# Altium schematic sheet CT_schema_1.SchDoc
size 750 x 499 mm
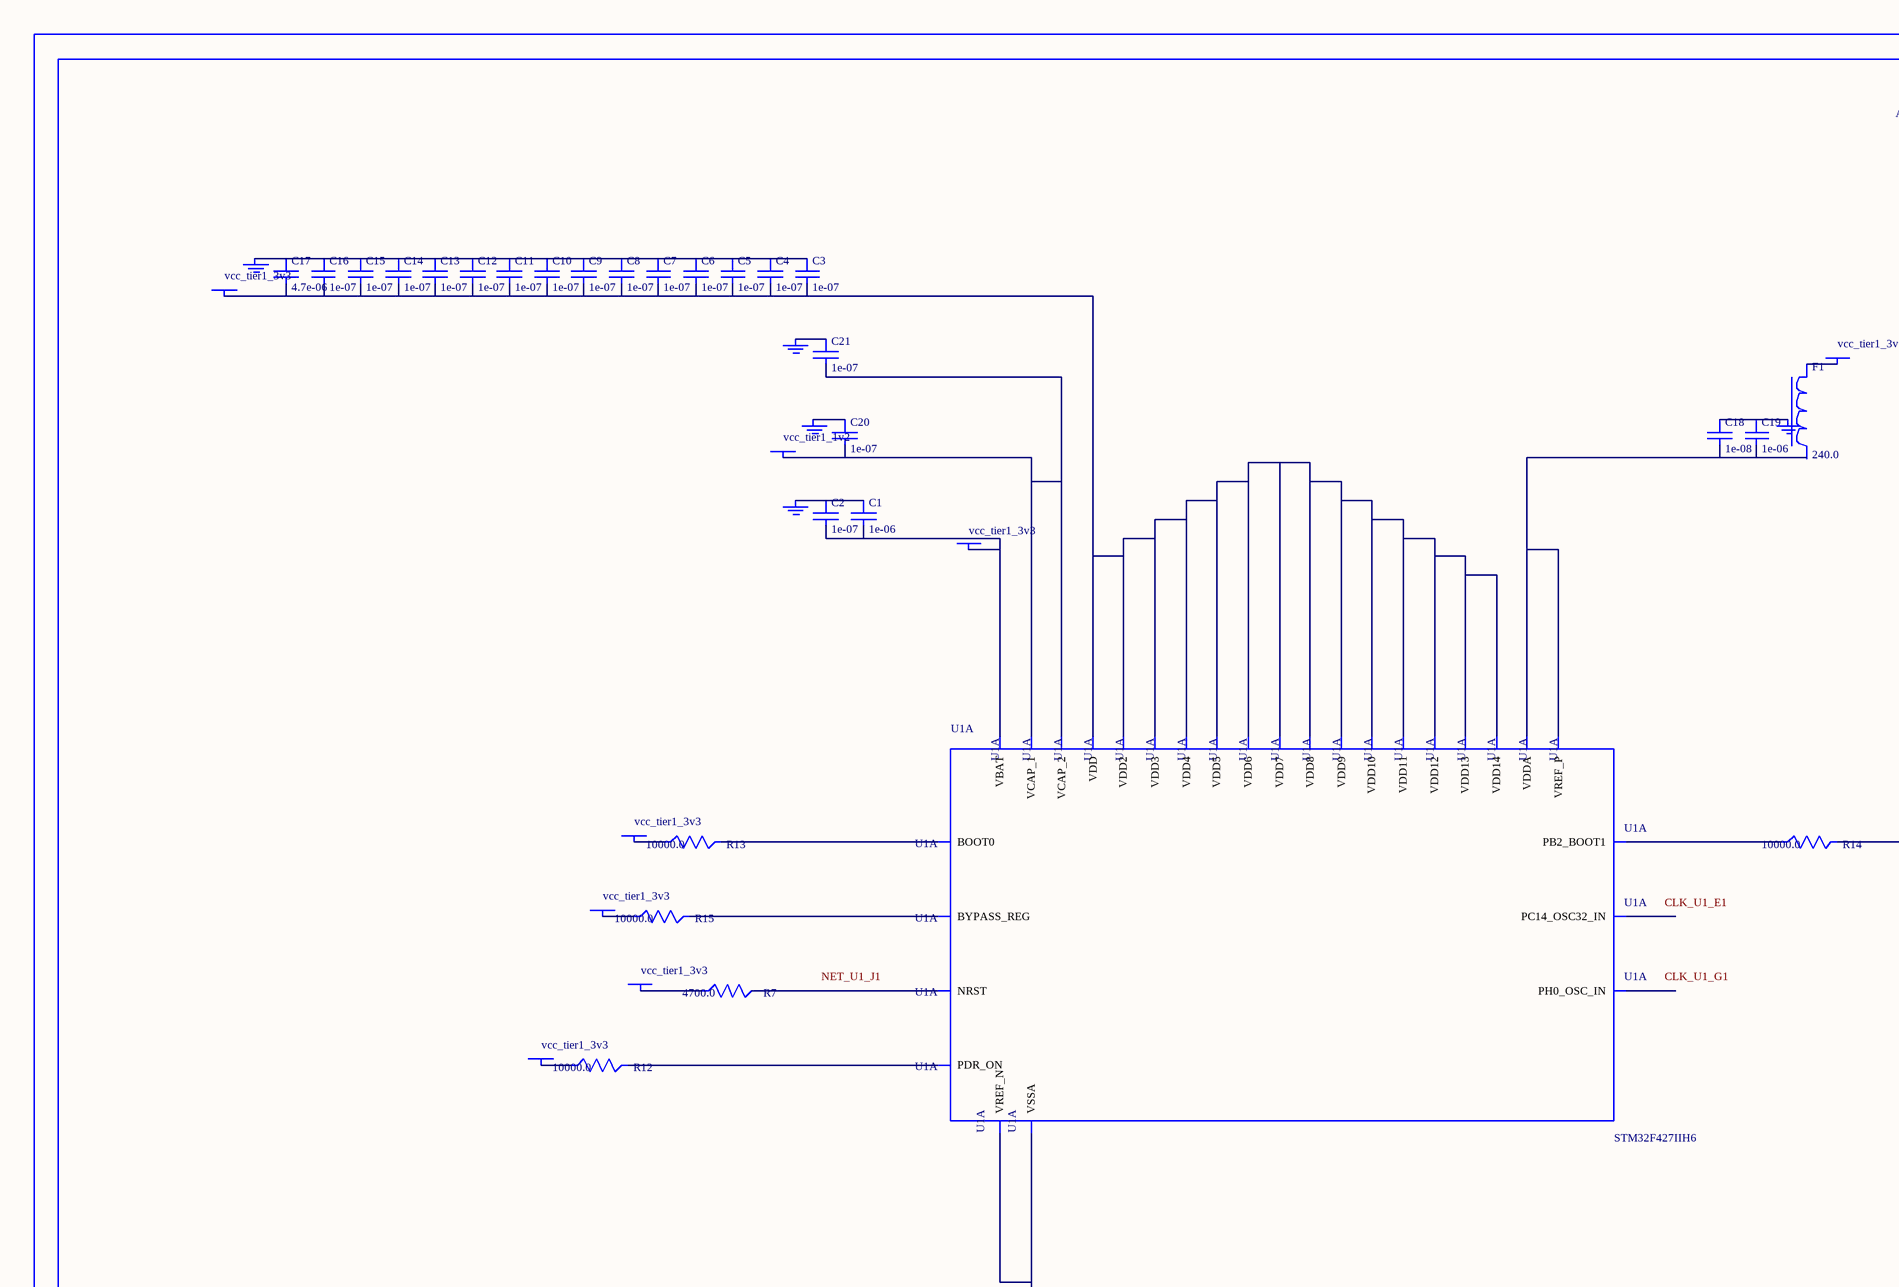
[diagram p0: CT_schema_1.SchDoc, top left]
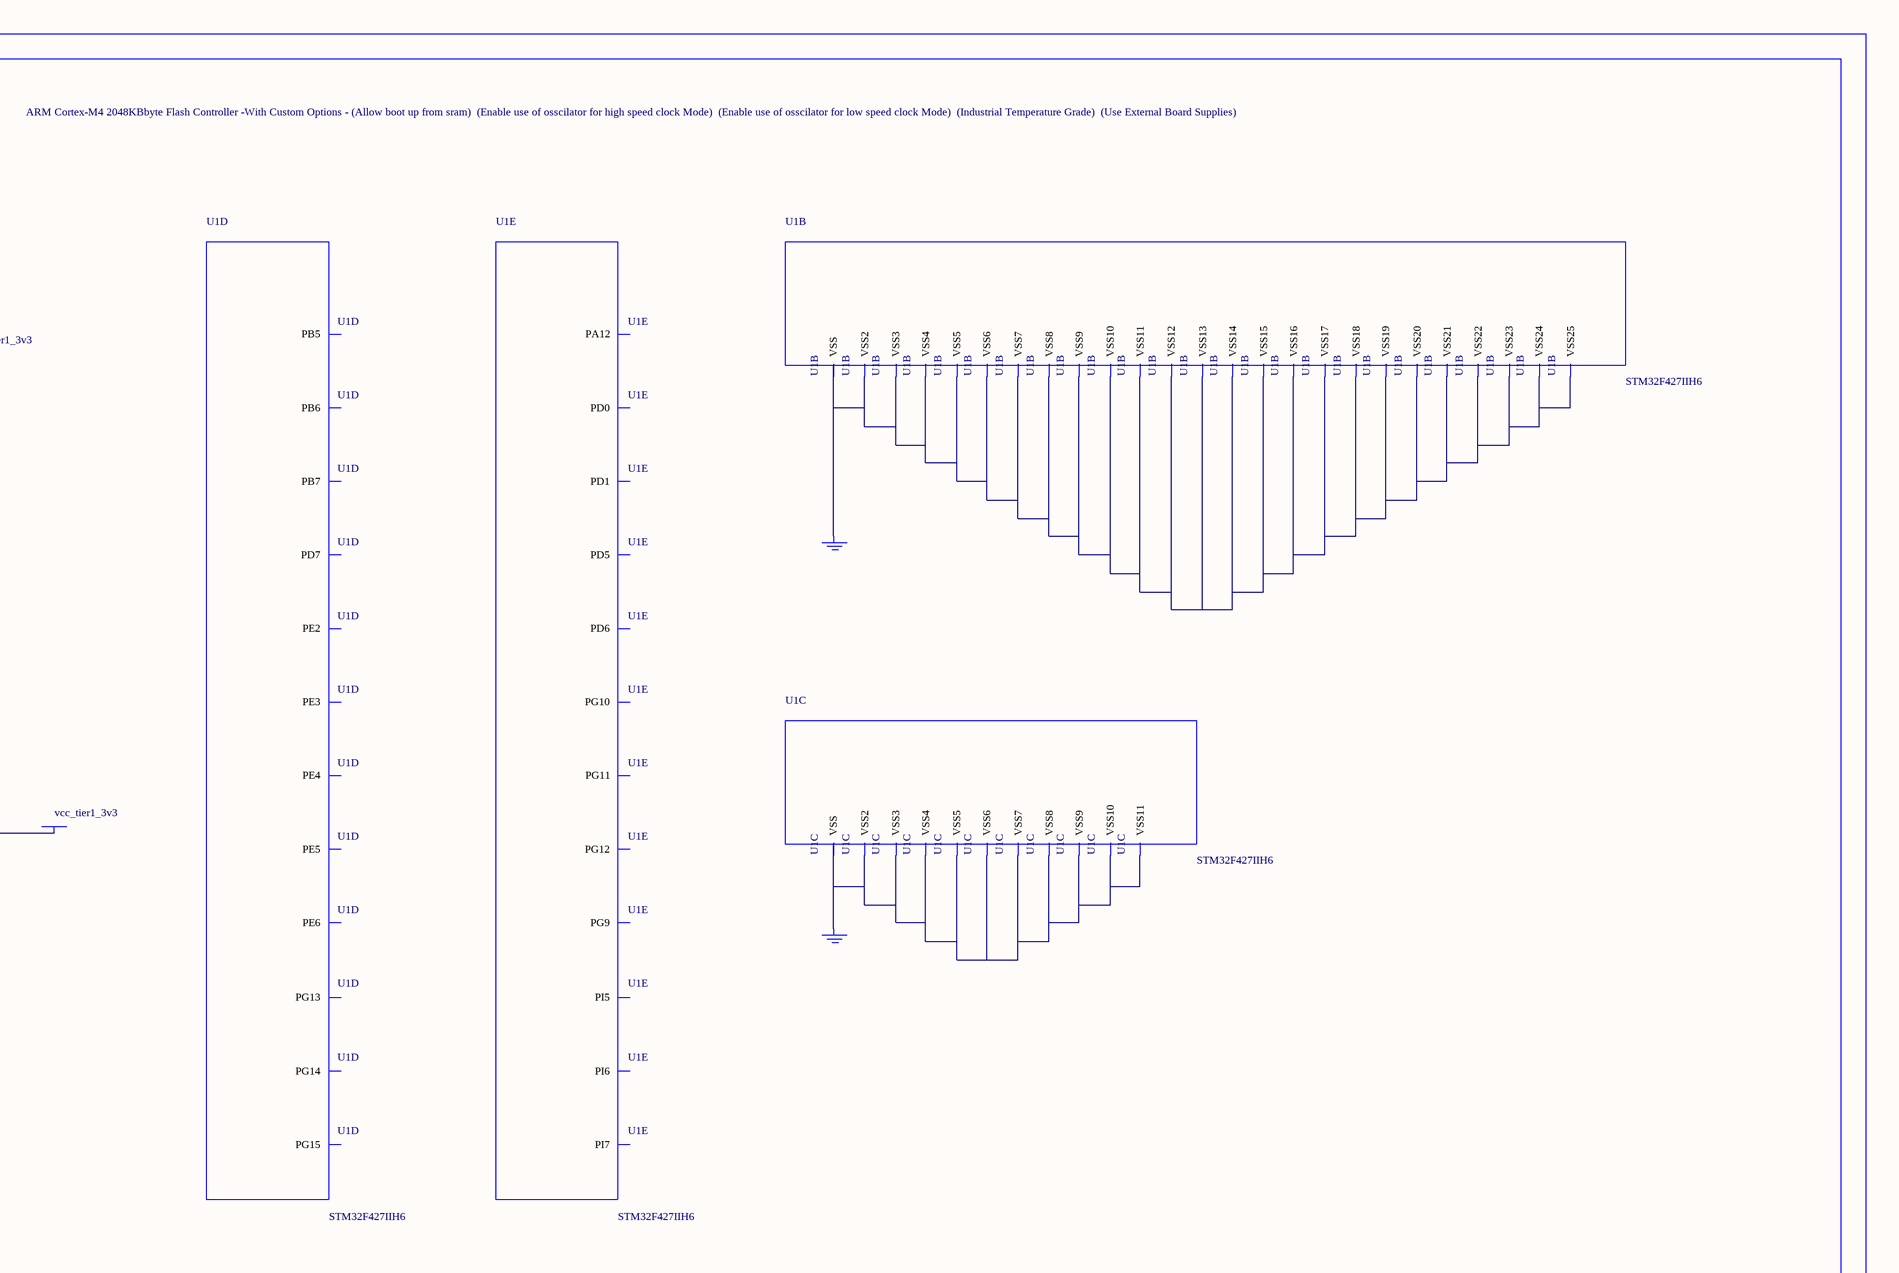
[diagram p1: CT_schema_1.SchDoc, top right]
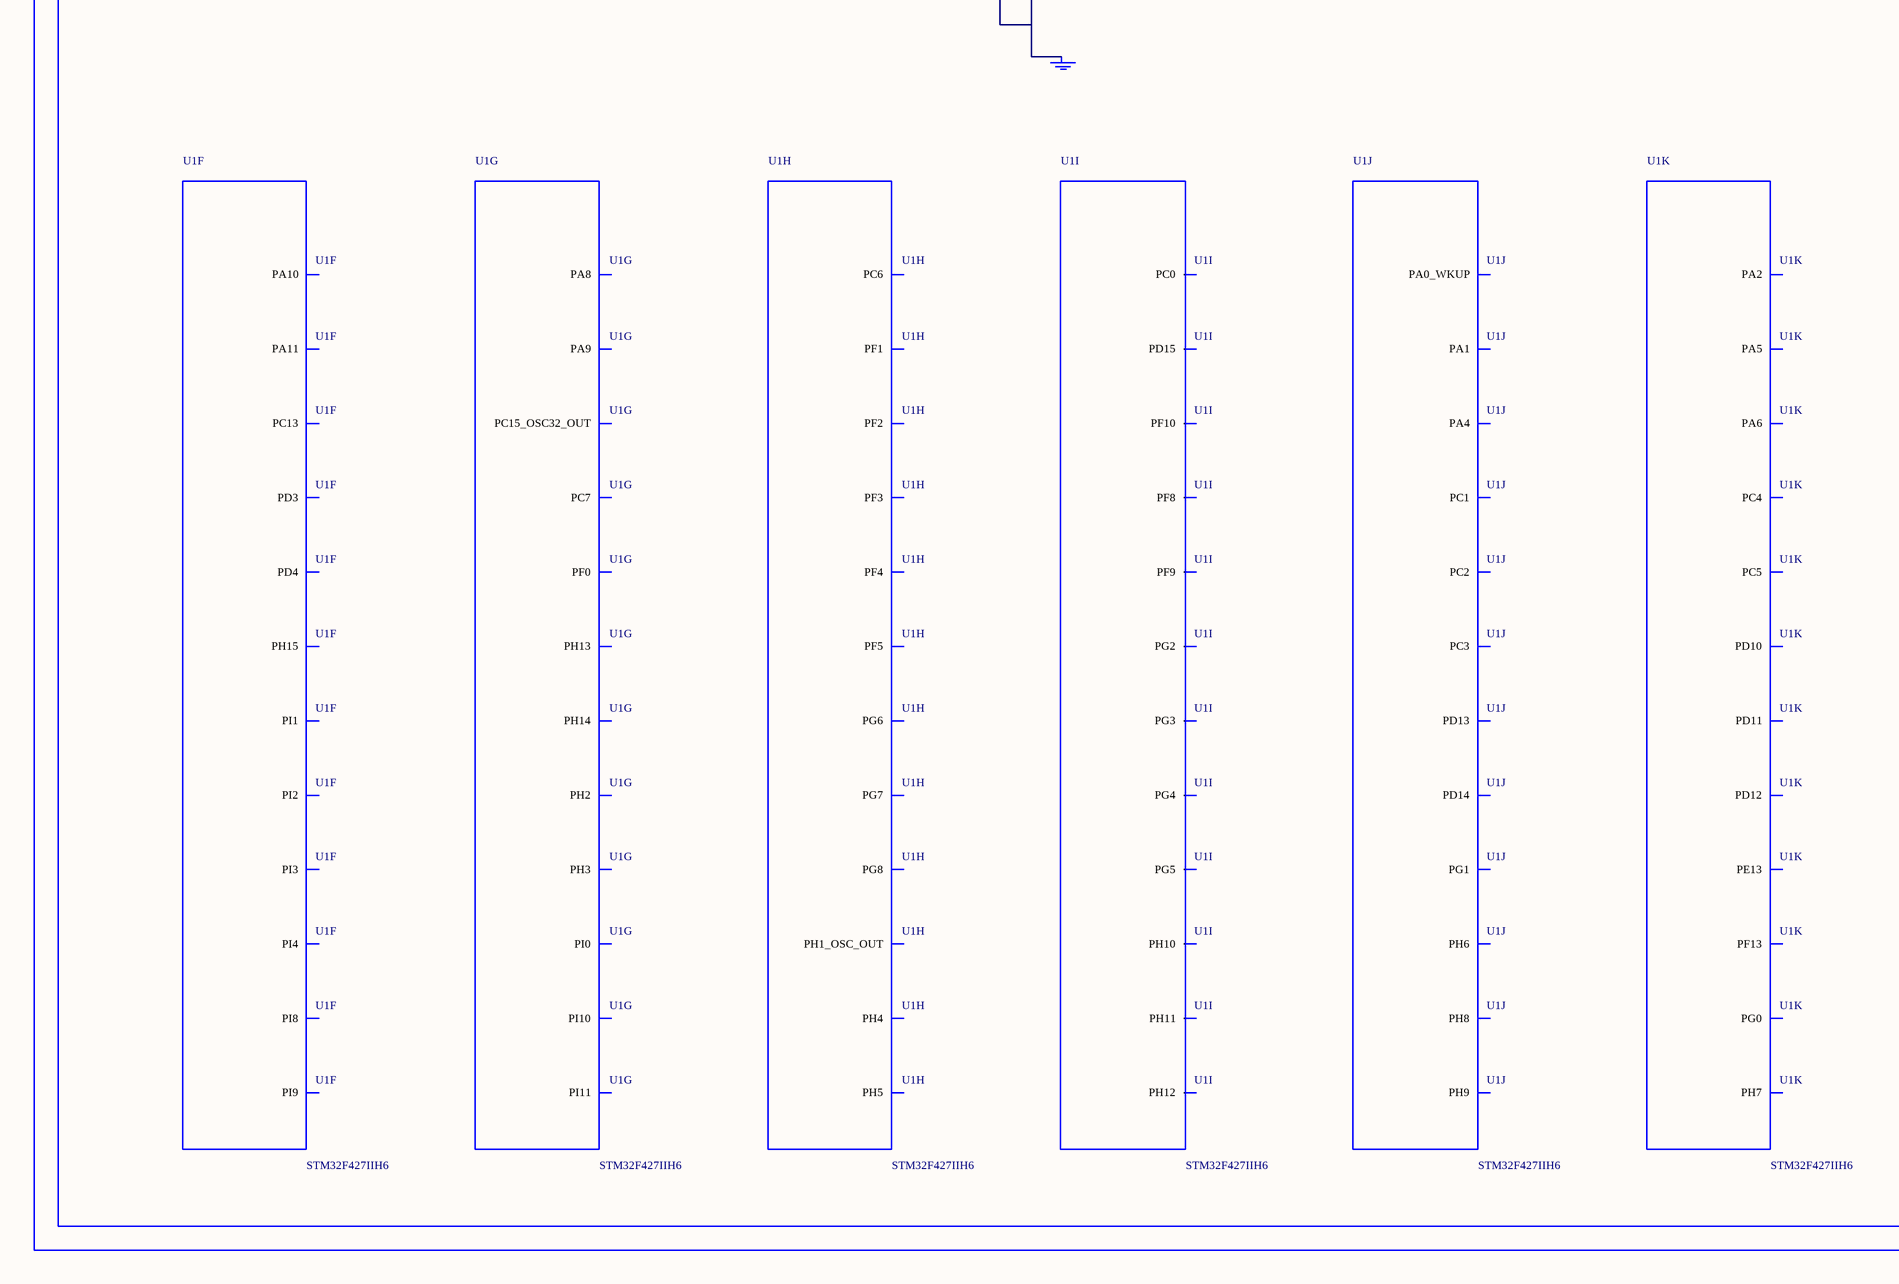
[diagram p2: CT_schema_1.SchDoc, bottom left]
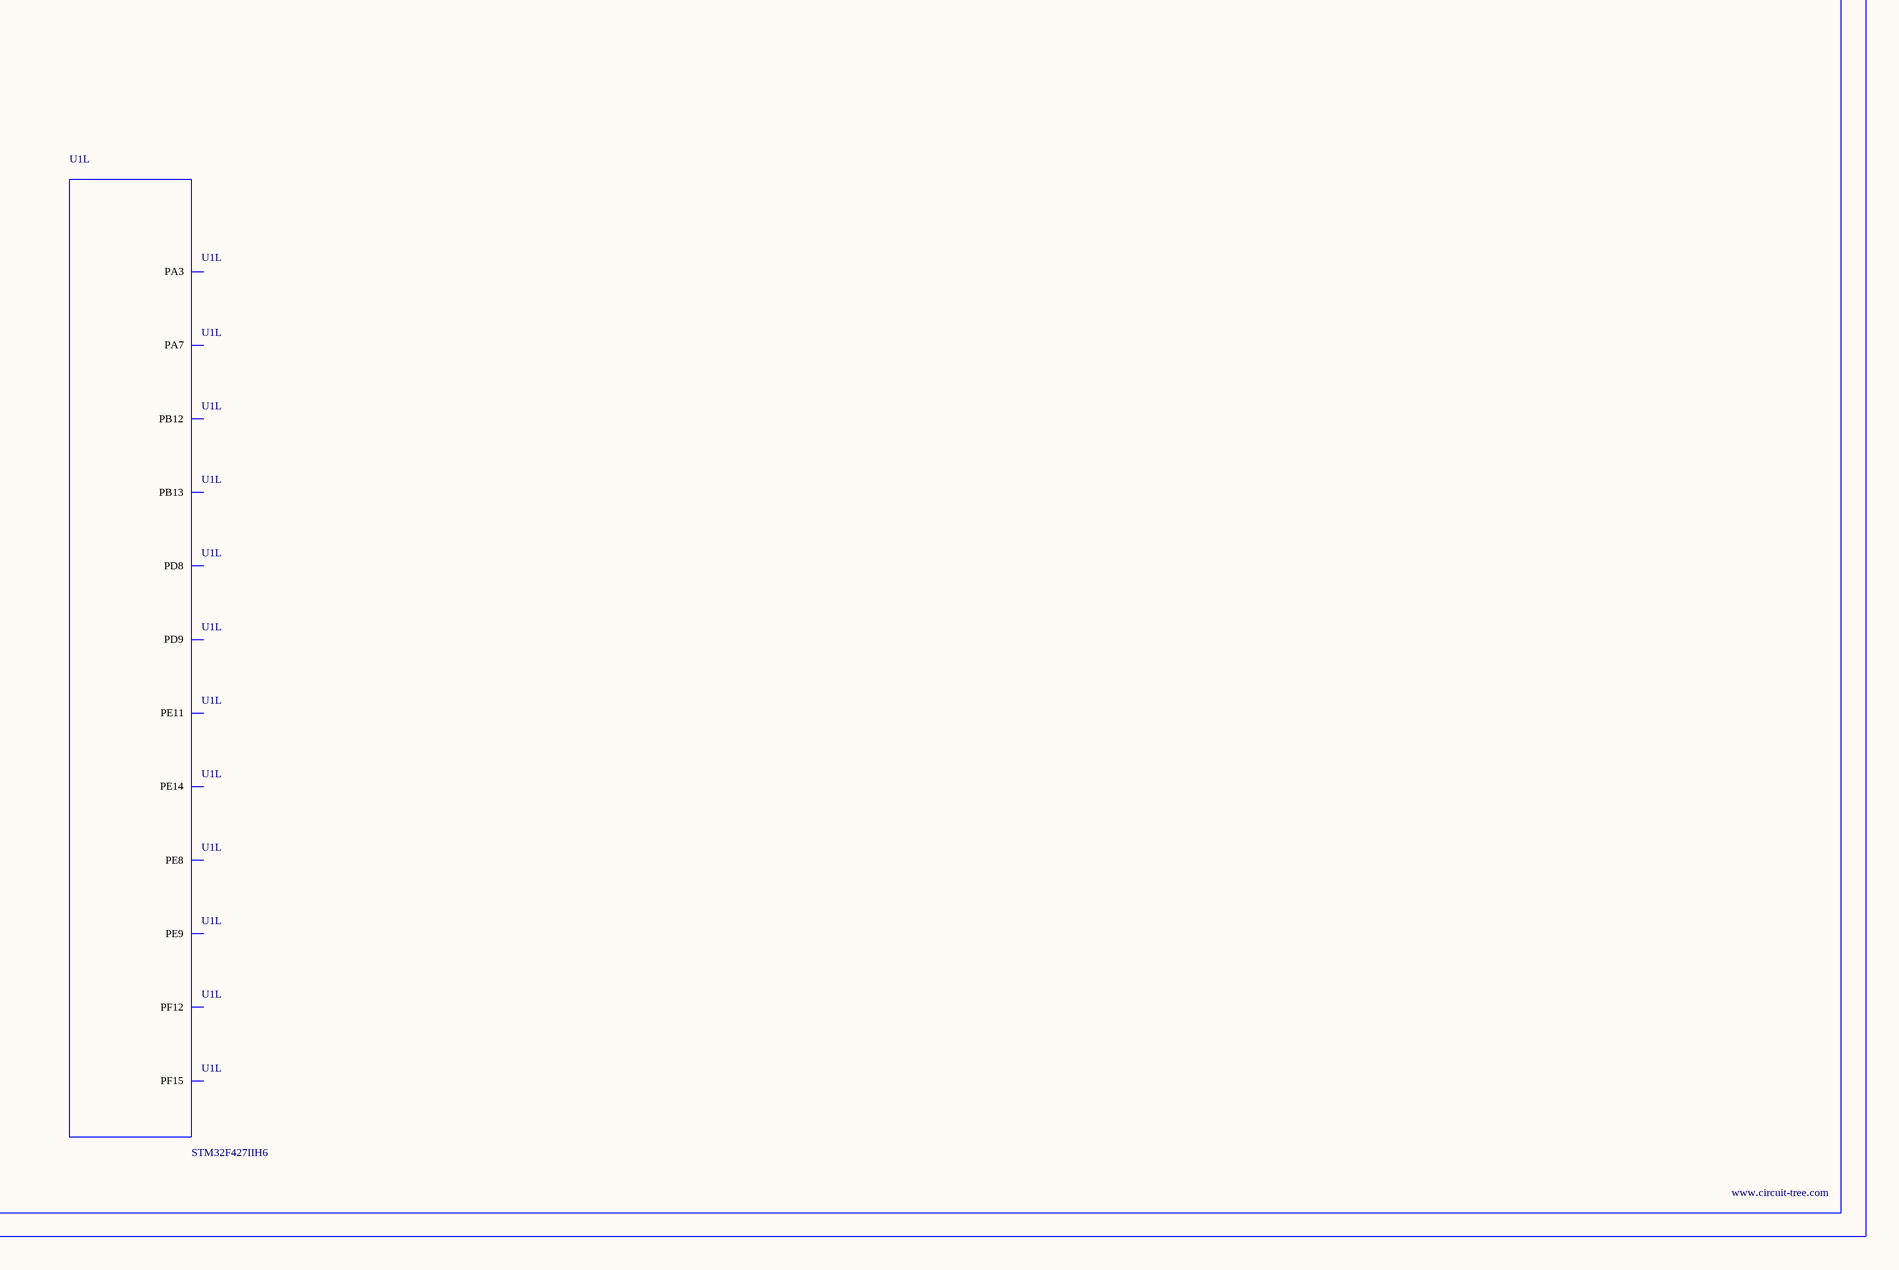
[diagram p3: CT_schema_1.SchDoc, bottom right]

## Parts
BORDER0  (no value)
C1  1e-06  [C0603]
C2  1e-07  [C0603]
C3  1e-07  [C0603]
C4  1e-07  [C0603]
C5  1e-07  [C0603]
C6  1e-07  [C0603]
C7  1e-07  [C0603]
C8  1e-07  [C0603]
C9  1e-07  [C0603]
C10  1e-07  [C0603]
C11  1e-07  [C0603]
C12  1e-07  [C0603]
C13  1e-07  [C0603]
C14  1e-07  [C0603]
C15  1e-07  [C0603]
C16  1e-07  [C0603]
C17  4.7e-06  [C0603]
C18  1e-08  [C0603]
C19  1e-06  [C0603]
C20  1e-07  [C0402]
C21  1e-07  [C0402]
F1  240.0  [L0603]
GND_INSTANCE_0_0  (no value)
GND_INSTANCE_0_1  (no value)
GND_INSTANCE_0_2  (no value)
GND_INSTANCE_0_3  (no value)
GND_INSTANCE_0_4  (no value)
GND_INSTANCE_0_5  (no value)
GND_INSTANCE_0_6  (no value)
GND_INSTANCE_0_7  (no value)
POWER_INSTANCE_0_0  vcc_tier1_3v3
POWER_INSTANCE_0_1  vcc_tier1_3v3
POWER_INSTANCE_0_2  vcc_tier1_3v3
POWER_INSTANCE_0_3  vcc_tier1_3v3
POWER_INSTANCE_0_4  vcc_tier1_3v3
POWER_INSTANCE_0_5  vcc_tier1_3v3
POWER_INSTANCE_0_6  vcc_tier1_3v3
POWER_INSTANCE_0_7  vcc_tier1_1v2
POWER_INSTANCE_0_8  vcc_tier1_3v3
R7  4700.0  [R0603]
R12  10000.0  [R0603]
R13  10000.0  [R0603]
R14  10000.0  [R0603]
R15  10000.0  [R0603]
U1  STM32F427IIH6  [UFBGA176_25]  (parts A,B,C,D,E,F,G,H,I,J,K,L of 17)

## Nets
NetC1_1: C1.1 C2.1 GND_INSTANCE_0_0.0(GND)
NetC1_2: C1.2 C2.2 POWER_INSTANCE_0_0.0(PWR) U1.C1(VBAT)
NetC3_1: C3.1 C4.1 C5.1 C6.1 C7.1 C8.1 C9.1 C10.1 C11.1 C12.1 C13.1 C14.1 C15.1 C16.1 C17.1 GND_INSTANCE_0_2.0(GND)
NetC3_2: C3.2 C4.2 C5.2 C6.2 C7.2 C8.2 C9.2 C10.2 C11.2 C12.2 C13.2 C14.2 C15.2 C16.2 C17.2 POWER_INSTANCE_0_2.0(PWR) U1.C5(VDD) U1.C7(VDD2) U1.C8(VDD3) U1.C9(VDD4) U1.F3(VDD5) U1.G3(VDD7) U1.G13(VDD6) U1.H13(VDD8) U1.J12(VDD9) U1.J13(VDD10) U1.K4(VDD11) U1.N8(VDD13) U1.N9(VDD14) U1.N10(VDD12)
NetC18_1: C18.1 C19.1 GND_INSTANCE_0_1.0(GND)
NetC18_2: C18.2 C19.2 U1.P1(VREF_P) U1.R1(VDDA)
NetC20_1: C20.1 GND_INSTANCE_0_3.0(GND)
NetC20_2: C20.2 C21.2 POWER_INSTANCE_0_7.0(PWR) U1.F13(VCAP_2) U1.M10(VCAP_1)
NetC21_1: C21.1 GND_INSTANCE_0_4.0(GND)
NetF1_1: F1.1 POWER_INSTANCE_0_1.0(PWR)
NetGND_INSTANCE_0_5_0: GND_INSTANCE_0_5.0(GND) U1.M1(VSSA) U1.N1(VREF_N)
NetGND_INSTANCE_0_6_0: GND_INSTANCE_0_6.0(GND) U1.D5(VSS) U1.D7(VSS2) U1.D8(VSS3) U1.D9(VSS4) U1.F2(VSS7) U1.F6(VSS8) U1.F7(VSS9) U1.F8(VSS10) U1.F9(VSS11) U1.F10(VSS5) U1.F12(VSS6) U1.G2(VSS14) U1.G6(VSS15) U1.G7(VSS16) U1.G8(VSS17) U1.G9(VSS18) U1.G10(VSS12) U1.G12(VSS13) U1.H6(VSS21) U1.H7(VSS22) U1.H8(VSS23) U1.H9(VSS24) U1.H10(VSS19) U1.H12(VSS20) U1.J10(VSS25)
NetGND_INSTANCE_0_7_0: GND_INSTANCE_0_7.0(GND) U1.J6(VSS) U1.J7(VSS2) U1.J8(VSS3) U1.J9(VSS4) U1.K6(VSS6) U1.K7(VSS7) U1.K8(VSS8) U1.K9(VSS9) U1.K10(VSS5) U1.M8(VSS10) U1.M9(VSS11)
NetPOWER_INSTANCE_0_3_0: POWER_INSTANCE_0_3.0(PWR) R12.1
NetPOWER_INSTANCE_0_4_0: POWER_INSTANCE_0_4.0(PWR) R13.1
NetPOWER_INSTANCE_0_5_0: POWER_INSTANCE_0_5.0(PWR) R14.2
NetPOWER_INSTANCE_0_6_0: POWER_INSTANCE_0_6.0(PWR) R15.1
NetPOWER_INSTANCE_0_8_0: POWER_INSTANCE_0_8.0(PWR) R7.1
NetR7_2: R7.2 U1.J1(NRST)
NetR12_2: R12.2 U1.C6(PDR_ON)
NetR13_2: R13.2 U1.D6(BOOT0)
NetR14_1: R14.1 U1.M6(PB2_BOOT1)
NetR15_2: R15.2 U1.L4(BYPASS_REG)

Not connected (* = marked no-connect by the designer): F1 2; U1 A1(PE3) A2(PE2) A6(PB5) A7(PG14) A8(PG13) A11(PD7) B1(PE4) B2(PE5) B3(PE6) B5(PB7) B6(PB6) B7(PG15) B8(PG12) B9(PG11) B10(PG10) B11(PD6) B12(PD0) B15(PA12) C2(PI7) C3(PI6) C4(PI5) C10(PG9) C11(PD5) C12(PD1) C13(PI3) C14(PI2) C15(PA11) D1(PC13) D2(PI8) D3(PI9) D4(PI4) D10(PD4) D11(PD3) D13(PH15) D14(PI1) D15(PA10) E1(PC14_OSC32_IN) E2(PF0) E3(PI10) E4(PI11) E12(PH13) E13(PH14) E14(PI0) E15(PA9) F1(PC15_OSC32_OUT) F4(PH2) F15(PA8) G1(PH0_OSC_IN) G4(PH3) G15(PC7) H1(PH1_OSC_OUT) H2(PF2) H3(PF1) H4(PH4) H14(PG8) H15(PC6) J2(PF3) J3(PF4) J4(PH5) J14(PG7) J15(PG6) K3(PF5) K12(PH12) K13(PG5) K14(PG4) K15(PG3) L1(PF10) L2(PF9) L3(PF8) L12(PH11) L13(PH10) L14(PD15) L15(PG2) M2(PC0) M3(PC1) M4(PC2) M5(PC3) M7(PG1) M11(PH6) M12(PH8) M13(PH9) M14(PD14) M15(PD13) N2(PA1) N3(PA0_WKUP) N4(PA4) N5(PC4) N6(PF13) N7(PG0) N11(PE13) N12(PH7) N13(PD12) N14(PD11) N15(PD10) P2(PA2) P3(PA6) P4(PA5) P5(PC5) P6(PF12) P7(PF15) P8(PE8) P9(PE9) P10(PE11) P11(PE14) P12(PB12) P13(PB13) P14(PD9) P15(PD8) R2(PA3) R3(PA7)

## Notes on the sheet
- Labels drawn without touching a wire or pin: CLK_U1_E1, CLK_U1_G1, NET_U1_J1

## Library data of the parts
BORDER0 = BORDER_PAGE0
C1 C19 = C0603C105K3RACTU
C2-C16 = 06035C104K4Z2A
C17 = GRM188R6YA475KE15D
C18 = 06035C103K4Z2A
C20 C21 = C0402C104K3RACTU
F1 = Z0603C241ASMST
GND_INSTANCE_0_0-GND_INSTANCE_0_7 = GND
POWER_INSTANCE_0_0-POWER_INSTANCE_0_8 = PWR
R7 = RC0603JR-074K7L
R12-R15 = RC0603JR-0710KL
